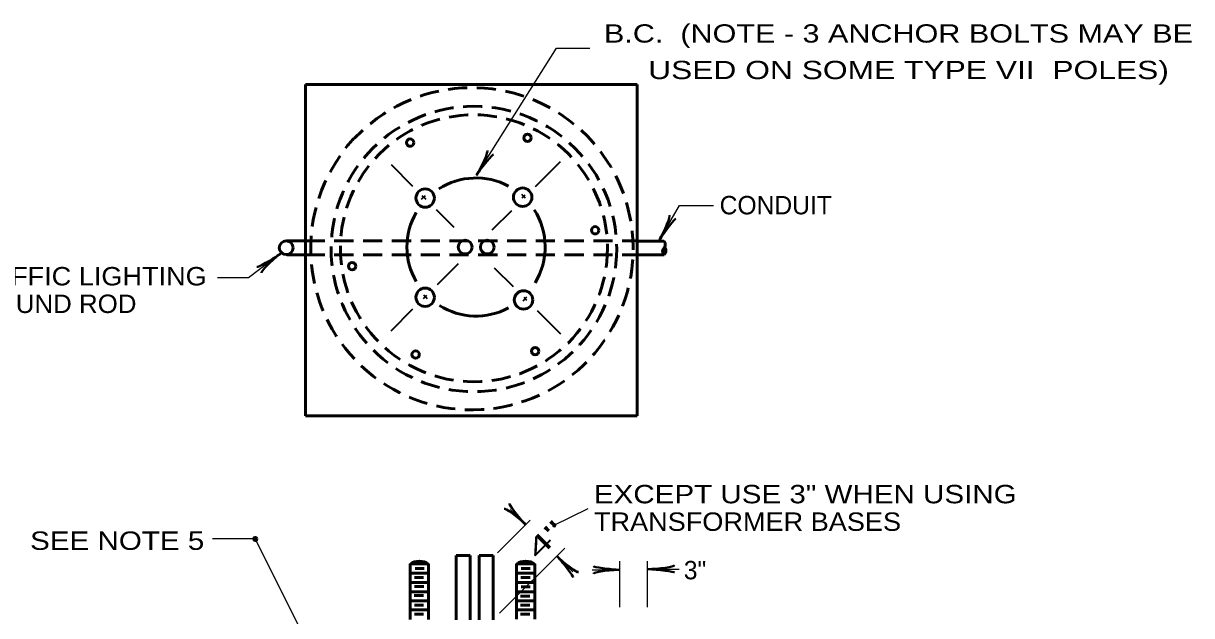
# Model space of a CAD drawing. Extents: x -1 to 679, y 0 to 440.
# Drawn here: x 300.7 to 428.5, y 128.7 to 193.5 of the extents above; entities that cross this region are included whole.
import ezdxf

# ---------------------------------------------------------------- set-up
doc = ezdxf.new("R2010")
doc.units = 0
doc.header["$LTSCALE"] = 0.7
doc.header["$PDMODE"] = 32
doc.header["$PDSIZE"] = 0.35
doc.linetypes.add('MEDIUM_DASHED', pattern=[4.5, 3, -1.5])
doc.layers.add('1', color=7, linetype='Continuous', lineweight=53)

msp = doc.modelspace()

# ---------------------------------------------------------------- linework, layer by layer
at = {"layer": '1'}
for p, q in [((331.5517, 186.8363), (331.5517, 150.5563)), ((331.5517, 186.8363), (367.8317, 186.8363)), ((367.8317, 186.8363), (367.8317, 150.5563)), ((329.5118, 169.7163), (331.5317, 169.7163)), ((367.7518, 169.6962), (370.7717, 169.6962)), ((329.5118, 168.1962), (331.5317, 168.1962)), ((367.7518, 168.1962), (370.7917, 168.1962)), ((331.5517, 150.5563), (367.8317, 150.5563)), ((343.0118, 134.3363), (343.0118, 128.2362)), ((343.0118, 134.3363), (345.0118, 134.3363)), ((345.0118, 134.3363), (345.0118, 128.2362)), ((348.0517, 135.2763), (348.0517, 128.2163)), ((348.0517, 135.2763), (349.5517, 135.2763)), ((349.5517, 135.2763), (349.5517, 128.2163)), ((350.5718, 135.2763), (350.5718, 128.2163)), ((350.5718, 135.2763), (352.0718, 135.2763)), ((352.0718, 135.2763), (352.0718, 128.2163)), ((354.6318, 134.3363), (354.6318, 128.2763)), ((354.6318, 134.3363), (356.6517, 134.3363)), ((356.6517, 134.3363), (356.6517, 128.2763)), ((343.0118, 133.3162), (345.0118, 133.3162)), ((343.5517, 133.8363), (344.5517, 133.8363)), ((354.6318, 133.3162), (356.6517, 133.3162)), ((355.1318, 133.8562), (356.1318, 133.8562)), ((343.0118, 132.3162), (345.0118, 132.3162)), ((343.4717, 132.8562), (344.4717, 132.8562)), ((343.4917, 131.8562), (344.4917, 131.8562)), ((354.6318, 132.3162), (356.6517, 132.3162)), ((355.1117, 132.8562), (356.1318, 132.8562)), ((355.1517, 131.8363), (356.1517, 131.8363)), ((343.0118, 131.2962), (345.0118, 131.2962)), ((343.4518, 130.8762), (344.4518, 130.8762)), ((354.6318, 131.2962), (356.6517, 131.2962)), ((355.0718, 130.7962), (356.0917, 130.7962)), ((343.0118, 130.2962), (345.0118, 130.2962)), ((343.0118, 129.2962), (345.0118, 129.2962)), ((343.4717, 129.8363), (344.4717, 129.8363)), ((354.6318, 130.2962), (356.6517, 130.2962)), ((354.6318, 129.2962), (356.6517, 129.2962)), ((355.0917, 129.8363), (356.1117, 129.8363)), ((343.4717, 128.8363), (344.4717, 128.8363)), ((355.0718, 128.8363), (356.0917, 128.8363))]:
    msp.add_line(p, q, dxfattribs=at)
at = {"layer": '1', "lineweight": 35}
for p, q in [((340.9117, 178.0762), (343.2717, 175.7163)), ((356.7317, 175.6762), (359.4518, 178.3962)), ((344.2518, 174.2763), (344.6717, 174.6962)), ((344.2917, 174.6962), (344.7117, 174.2763)), ((355.1918, 174.8363), (355.5917, 174.4363)), ((355.2518, 174.4162), (355.5917, 174.7562)), ((345.8517, 173.1362), (347.7917, 171.1962)), ((351.9917, 170.9363), (354.1318, 173.0563)), ((345.9917, 164.9363), (348.2917, 167.2362)), ((352.2117, 166.7763), (354.2717, 164.7163)), ((344.4518, 163.7962), (344.8717, 163.3962)), ((344.4717, 163.4162), (344.8117, 163.7562)), ((355.3717, 163.1562), (355.7717, 163.5762)), ((355.4518, 163.5362), (355.7518, 163.2362)), ((340.9117, 159.8562), (343.3117, 162.2562)), ((356.8918, 162.0962), (359.4518, 159.5362))]:
    msp.add_line(p, q, dxfattribs=at)
at = {"layer": '1', "linetype": 'MEDIUM_DASHED'}
for p, q in [((331.5517, 169.7163), (367.8317, 169.7163)), ((331.5517, 168.1962), (367.8317, 168.1962))]:
    msp.add_line(p, q, dxfattribs=at)
at = {"layer": '1', "lineweight": 25}
for p, q in [((353.9518, 140.3162), (355.6318, 138.6362)), ((358.7518, 138.5762), (362.4717, 140.3963)), ((352.5718, 135.5563), (356.1318, 139.1163)), ((326.0517, 137.0762), (321.3717, 137.0762)), ((337.7117, 113.7762), (326.0517, 137.0762)), ((352.7917, 128.9363), (359.9317, 136.0762)), ((359.0517, 135.1962), (360.8117, 133.4562)), ((365.9518, 129.6163), (365.9518, 134.6562)), ((368.9717, 129.6163), (368.9717, 134.6562)), ((362.9317, 133.6962), (365.9518, 133.6962)), ((369.0118, 133.7763), (372.4518, 133.7763))]:
    msp.add_line(p, q, dxfattribs=at)
for points in [[(350.2518, 176.9162), (359.0317, 190.8162), (362.6517, 190.8162)], [(370.2917, 169.8162), (372.4717, 173.5962), (376.1918, 173.5962)], [(328.7917, 168.2962), (325.3117, 165.6562), (321.9117, 165.6562)]]:
    msp.add_lwpolyline(points, dxfattribs=at)
at = {"layer": '1', "linetype": 'MEDIUM_DASHED'}
for centre, radius in [((349.9778, 168.8248), 15.624), ((349.9778, 168.9004), 14.616)]:
    msp.add_circle(centre, radius, dxfattribs=at)
at = {"layer": '1'}
for centre, radius in [((342.9946, 180.4705), 0.4032), ((355.846, 180.9996), 0.4032), ((344.645, 174.3983), 1.008), ((355.3138, 174.4944), 1.008), ((363.2545, 170.8697), 0.4032), ((329.44, 168.9604), 0.756), ((349.0195, 169.036), 0.756), ((351.4386, 169.036), 0.756), ((336.6445, 166.9387), 0.4032), ((344.645, 163.5373), 1.008), ((355.4099, 163.2489), 1.008), ((343.5993, 157.2623), 0.4032), ((356.6775, 157.6403), 0.4032), ((358.768, 138.5609), 0.0792)]:
    msp.add_circle(centre, radius, dxfattribs=at)
at = {"layer": '1', "linetype": 'MEDIUM_DASHED'}
for centre, radius, start, end in [((349.7605, 168.8516), 17.64, 144.72797, 134.59975), ((344.3332, 173.46), 10.5666, 131.18966, 148.13779)]:
    msp.add_arc(centre, radius, start, end, dxfattribs=at)
at = {"layer": '1'}
for centre, radius, start, end in [((350.214, 169.0408), 7.56, 61.93145, 122.73056), ((350.214, 169.0408), 7.56, 150.00307, 209.99693), ((350.214, 169.0408), 7.56, 328.65081, 32.73064), ((350.214, 169.0408), 7.56, 237.9532, 298.03362), ((344.011, 132.8615), 1.7783, 55.47029, 124.52971), ((355.6347, 132.8615), 1.7783, 55.47029, 124.52971)]:
    msp.add_arc(centre, radius, start, end, dxfattribs=at)
at = {"layer": '1', "lineweight": 40}
for centre, major_axis, ratio, start_param, end_param in [((350.6035, 177.9962), (-0.8277, -1.6061), 0.122415, 0.89635335, 3.14159265), ((351.0351, 177.7586), (1.0948, 1.4027), 0.07063, 6.28230741, 8.55970261), ((370.5959, 170.9026), (-0.7669, -1.636), 0.122415, 0.89635335, 3.14159265), ((371.0361, 170.6814), (-1.0415, -1.4427), 0.07063, 3.14071475, 5.41810995), ((327.7544, 167.7853), (1.5162, 0.9312), 0.07063, 3.14071475, 5.41810995), ((328.0757, 167.4118), (1.3372, 1.2152), 0.122415, 0.89635335, 3.14159265), ((354.9839, 139.5857), (-1.1267, 1.3771), 0.07063, 6.28230741, 8.55970261), ((354.9874, 139.576), (-1.1267, 1.3771), 0.07063, 6.28230741, 8.55970261), ((354.657, 139.2171), (1.3841, -1.1615), 0.122415, 0.89635335, 3.14159265), ((354.6605, 139.2073), (1.3841, -1.1615), 0.122415, 0.89635335, 3.14159265), ((359.6996, 134.2468), (1.1267, -1.3771), 0.07063, 6.28230741, 8.55970261), ((359.7047, 134.2554), (1.1267, -1.3771), 0.07063, 6.28230741, 8.55970261), ((360.0265, 134.6154), (-1.3841, 1.1615), 0.122415, 0.89635335, 3.14159265), ((360.0315, 134.624), (-1.3841, 1.1615), 0.122415, 0.89635335, 3.14159265), ((364.8516, 133.4191), (1.8, 0.1574), 0.122415, 0.89635335, 3.14159265), ((364.8221, 133.9109), (-1.7705, 0.1771), 0.07063, 6.28230741, 8.55970261), ((370.1442, 133.5599), (1.7705, -0.1771), 0.07063, 6.28230741, 8.55970261), ((370.1147, 134.0517), (-1.8, -0.1574), 0.122415, 0.89635335, 3.14159265)]:
    msp.add_ellipse(centre, major_axis=major_axis, ratio=ratio, start_param=start_param, end_param=end_param, dxfattribs=at)
at = {"layer": '1'}
for centre, major_axis, ratio, start_param, end_param in [((371.204, 168.6408), (-0.4377, -0.4364), 0.84388, 4.71240915, 6.33495284), ((370.3393, 169.2645), (0.4364, 0.4377), 0.896364, 4.67322481, 6.28318531), ((370.4102, 168.5983), (0.4364, 0.4377), 0.896364, 4.67322481, 6.28318531)]:
    msp.add_ellipse(centre, major_axis=major_axis, ratio=ratio, start_param=start_param, end_param=end_param, dxfattribs=at)
msp.add_spline([(358.7518, 138.5962), (358.7518, 138.5762), (358.7518, 138.5563), (358.7717, 138.5362), (358.7917, 138.5362), (358.8117, 138.5362), (358.7917, 138.5762), (358.7717, 138.5762), (358.7317, 138.5762), (358.7317, 138.5362), (358.7717, 138.5962), (358.7717, 138.5762), (358.7717, 138.5362), (358.7518, 138.5162), (358.7518, 138.5762), (358.7717, 138.5762), (358.8117, 138.5762), (358.7717, 138.5962), (358.7317, 138.5762), (358.7717, 138.5162), (358.7717, 138.5962), (358.7717, 138.5762), (358.7518, 138.5762), (358.7518, 138.6163), (358.7717, 138.5762), (358.7518, 138.5762), (358.7317, 138.5762), (358.7717, 138.5563)], degree=3, dxfattribs=at)
msp.add_point((326.0517, 137.0762), dxfattribs=at)

# ---------------------------------------------------------------- texts
for s, height, width, p in [('B.C.  (NOTE - 3 ANCHOR BOLTS MAY BE', 2, 1.25, (364.2117, 191.4243)), ('     USED ON SOME TYPE VII  POLES)', 2, 1.3, (364.2117, 187.4243)), ('TRAFFIC LIGHTING', 2.016, 1.1, (293.3918, 164.8363)), ('GROUND ROD', 2.016, 1.05, (293.3918, 161.8162)), ('EXCEPT USE 3" WHEN USING', 2.016, 1.2, (363.1117, 140.9762)), ('TRANSFORMER BASES', 2.016, 1.1, (363.1117, 137.9603)), ('SEE NOTE 5', 2.016, 1.2, (301.4117, 135.8762))]:
    msp.add_text(s, height=height, dxfattribs=dict(at, width=width)).set_placement(p)
for s, p in [('CONDUIT', (376.8717, 172.6163)), ('3"', (372.9518, 132.6562))]:
    msp.add_text(s, height=2.016, dxfattribs=at).set_placement(p)
at = {"layer": '1', "width": 1.8}
msp.add_text('4"', height=2.016, rotation=45, dxfattribs=at).set_placement((356.9518, 134.7562))

doc.saveas('drawing.dxf')
